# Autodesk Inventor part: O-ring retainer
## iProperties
Shininess: 64.0
Length Units: 11272
Angle Units: 11279
Time Units: 11290
Mass Units: 11286
Length Display Precision: 3
Angle Display Precision: 2
Compacted: True
Part Number: O-ring retainer
Document SubType Name: Modeling
Created: 2003-08
Designer: FT User
Manufacturer: Standard
Standards Organization: Custom
Density: 0.0
Volumn: 0.0
Area: 0.0
PropertySet Name: Model Information
Control State: 0
Master: False
Checked Out: False
Author: FT User
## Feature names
1. Extrusion4
2. Extrusion5
